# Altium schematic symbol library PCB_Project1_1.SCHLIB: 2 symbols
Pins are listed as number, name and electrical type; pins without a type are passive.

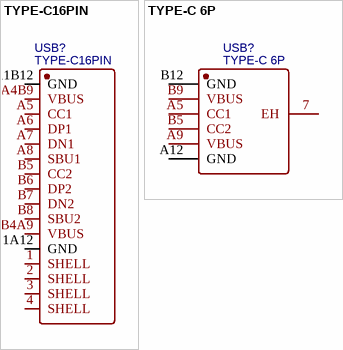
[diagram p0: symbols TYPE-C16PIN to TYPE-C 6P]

## TYPE-C16PIN
designator USB?
BOM_Manufacturer: SHOU HAN; Contributor: LCSC
footprint USB-C-SMD_TYPE-C16PIN
pins: 1 SHELL, 2 SHELL, 3 SHELL, 4 SHELL, A1B12 GND, A4B9 VBUS, A5 CC1, A6 DP1, A7 DN1, A8 SBU1, B1A12 GND, B4A9 VBUS, B5 CC2, B6 DP2, B7 DN2, B8 SBU2

## TYPE-C 6P
designator USB?
BOM_Manufacturer: SHOU HAN; Contributor: LCSC
footprint TYPE-C-SMD_TYPE-C-6P
pins: 7 EH, A5 CC1, A9 VBUS, A12 GND, B5 CC2, B9 VBUS, B12 GND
